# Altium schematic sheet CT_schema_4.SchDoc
size 312 x 238 mm
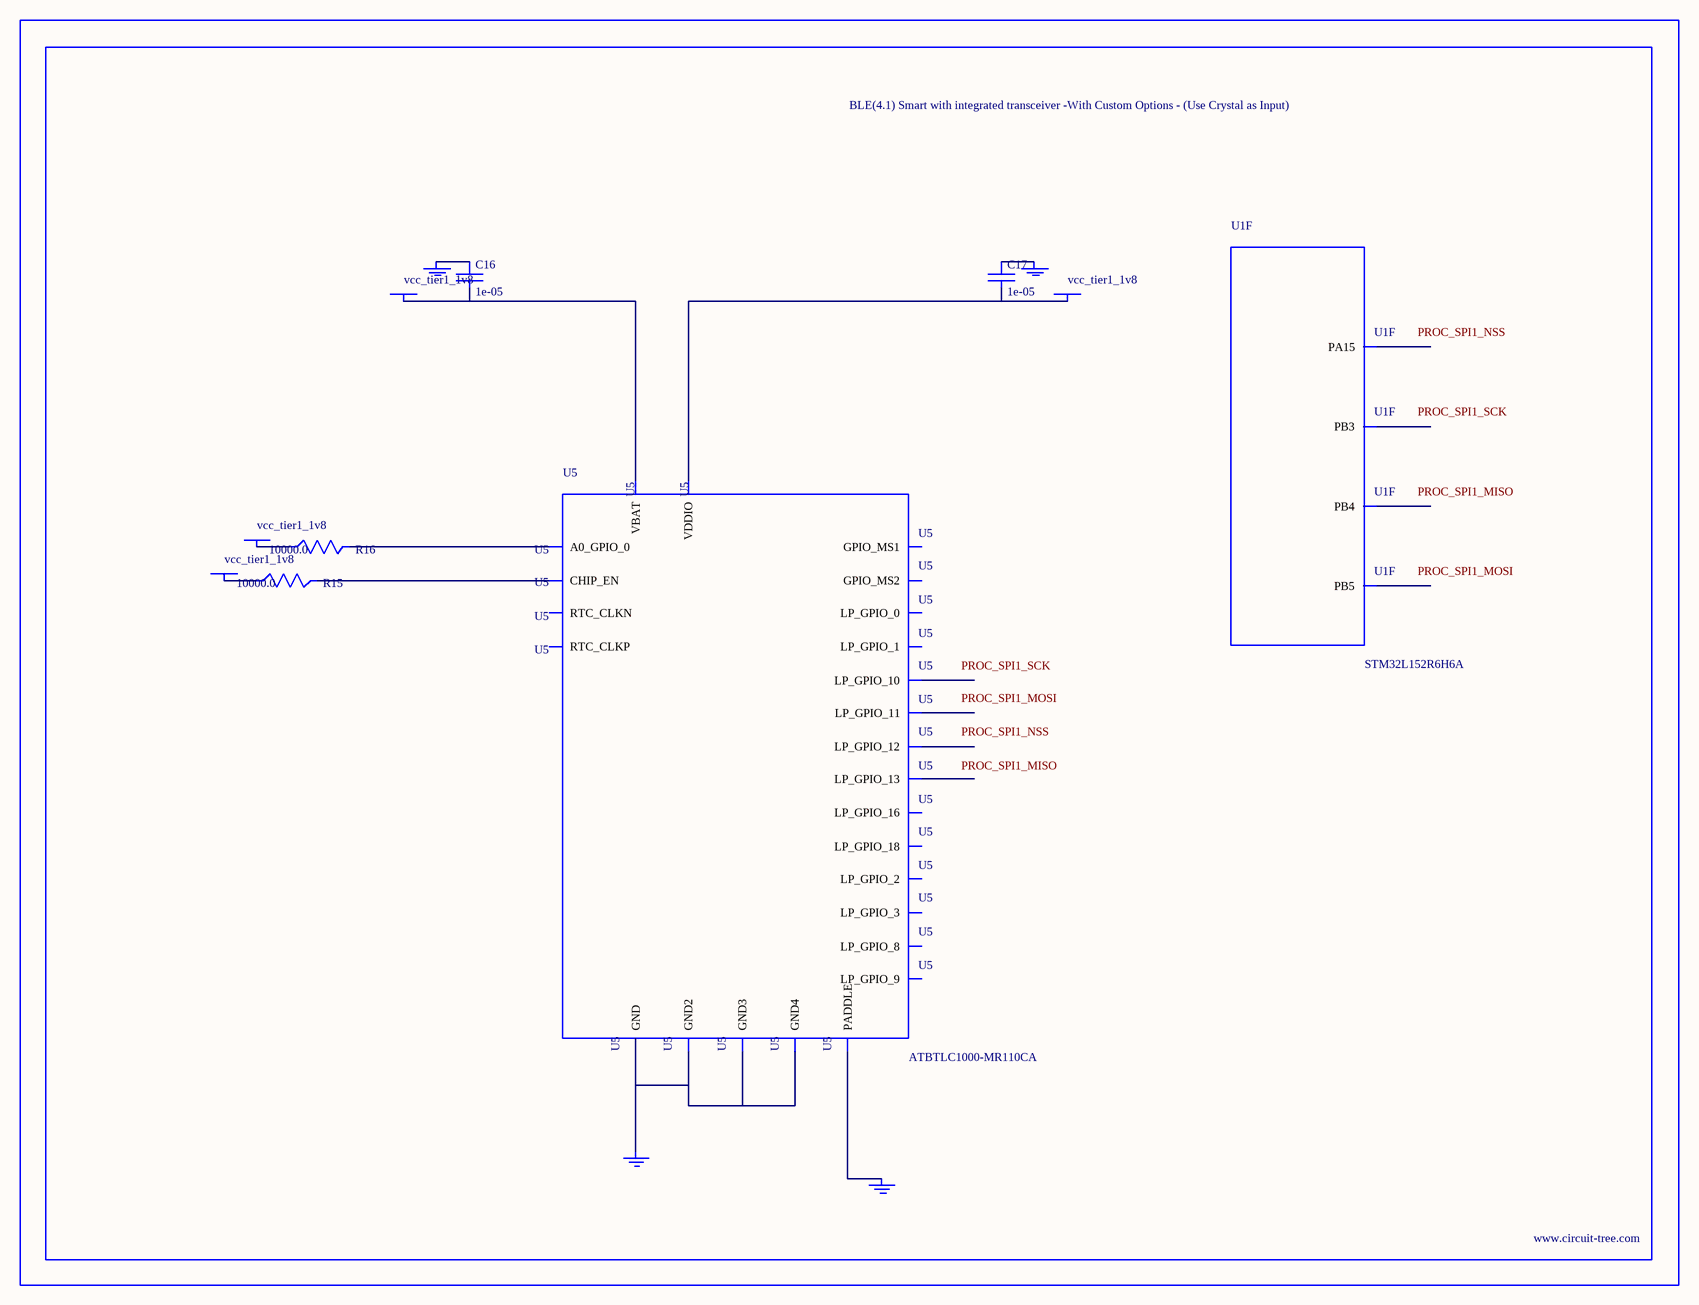
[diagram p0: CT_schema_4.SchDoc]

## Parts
BORDER3  (no value)
C16  1e-05  [C0805]
C17  1e-05  [C0805]
GND_INSTANCE_3_0  (no value)
GND_INSTANCE_3_1  (no value)
GND_INSTANCE_3_2  (no value)
GND_INSTANCE_3_3  (no value)
POWER_INSTANCE_3_0  vcc_tier1_1v8
POWER_INSTANCE_3_1  vcc_tier1_1v8
POWER_INSTANCE_3_2  vcc_tier1_1v8
POWER_INSTANCE_3_3  vcc_tier1_1v8
R15  10000.0  [R0603]
R16  10000.0  [R0603]
U1  STM32L152R6H6A  [TFBGA64]  (part F of 7)
U5  ATBTLC1000-MR110CA  [ATBTLC1000-MR110CA]

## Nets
NetC16_1: C16.1 GND_INSTANCE_3_0.0(GND)
NetC16_2: C16.2 POWER_INSTANCE_3_0.0(PWR) U5.6(VBAT)
NetC17_1: C17.1 GND_INSTANCE_3_1.0(GND)
NetC17_2: C17.2 POWER_INSTANCE_3_3.0(PWR) U5.22(VDDIO)
NetGND_INSTANCE_3_2_0: GND_INSTANCE_3_2.0(GND) U5.25(PADDLE)
NetGND_INSTANCE_3_3_0: GND_INSTANCE_3_3.0(GND) U5.1(GND) U5.9(GND2) U5.13(GND3) U5.24(GND4)
NetPOWER_INSTANCE_3_1_0: POWER_INSTANCE_3_1.0(PWR) R15.1
NetPOWER_INSTANCE_3_2_0: POWER_INSTANCE_3_2.0(PWR) R16.1
NetR15_2: R15.2 U5.17(CHIP_EN)
NetR16_2: R16.2 U5.20(A0_GPIO_0)

Not connected (* = marked no-connect by the designer): U1 A4(PB4) A5(PB3) A6(PA15) C4(PB5); U5 2(LP_GPIO_0) 3(LP_GPIO_1) 4(LP_GPIO_2) 5(LP_GPIO_3) 7(LP_GPIO_8) 8(LP_GPIO_9) 10(LP_GPIO_10) 11(LP_GPIO_11) 12(LP_GPIO_12) 14(LP_GPIO_13) 15(GPIO_MS1) 16(GPIO_MS2) 18(RTC_CLKP) 19(RTC_CLKN) 21(LP_GPIO_16) 23(LP_GPIO_18)

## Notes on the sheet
- Labels drawn without touching a wire or pin: PROC_SPI1_MISO, PROC_SPI1_MOSI, PROC_SPI1_NSS, PROC_SPI1_SCK

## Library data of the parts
BORDER3 = BORDER_PAGE3
C16 C17 = C0805C106K8RACTU
GND_INSTANCE_3_0-GND_INSTANCE_3_3 = GND
POWER_INSTANCE_3_0-POWER_INSTANCE_3_3 = PWR
R15 R16 = RC0603JR-0710KL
